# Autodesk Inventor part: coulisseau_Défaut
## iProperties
Shininess: 64.0
Length Units: 11269
Angle Units: 11279
Time Units: 11290
Mass Units: 11283
Length Display Precision: 3
Angle Display Precision: 2
Compacted: True
Part Number: coulisseau_Défaut
Document SubType Name: Modeling
Created: 2006-11
Material: Par défaut
Designer: profs_sti
Density: 0.0
Volumn: 0.0
Area: 0.0
PropertySet Name: Model Information
Control State: 0
Master: False
Checked Out: False
Author: profs_sti
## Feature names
1. Base1
